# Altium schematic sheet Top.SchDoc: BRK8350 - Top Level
size C; Organization: Opal Kelly; Address1: 13500 SW 72nd Ave STE 100; Address3: Portland, OR  97223; Address4: http://www.opalkelly.com; DocumentNumber: xxx; Revision: 1; SheetNumber: 1; SheetTotal: 7; PageSetup: Record=PageOptions¦CenterHorizontal=True¦CenterVertical=True¦PrintScale=0.52¦XCorrection=1.00¦YCorrection=1.00¦PrintKind=0¦BorderSize=5000000¦LeftOffset=0¦BottomOffset=0¦Orientation=2¦PaperLength=1000¦PaperWidth=1000¦Scale=100¦PaperSource=15¦PrintQuality=600¦MediaType=1¦DitherType=10¦PaperKind=Letter¦PrintScaleMode=1
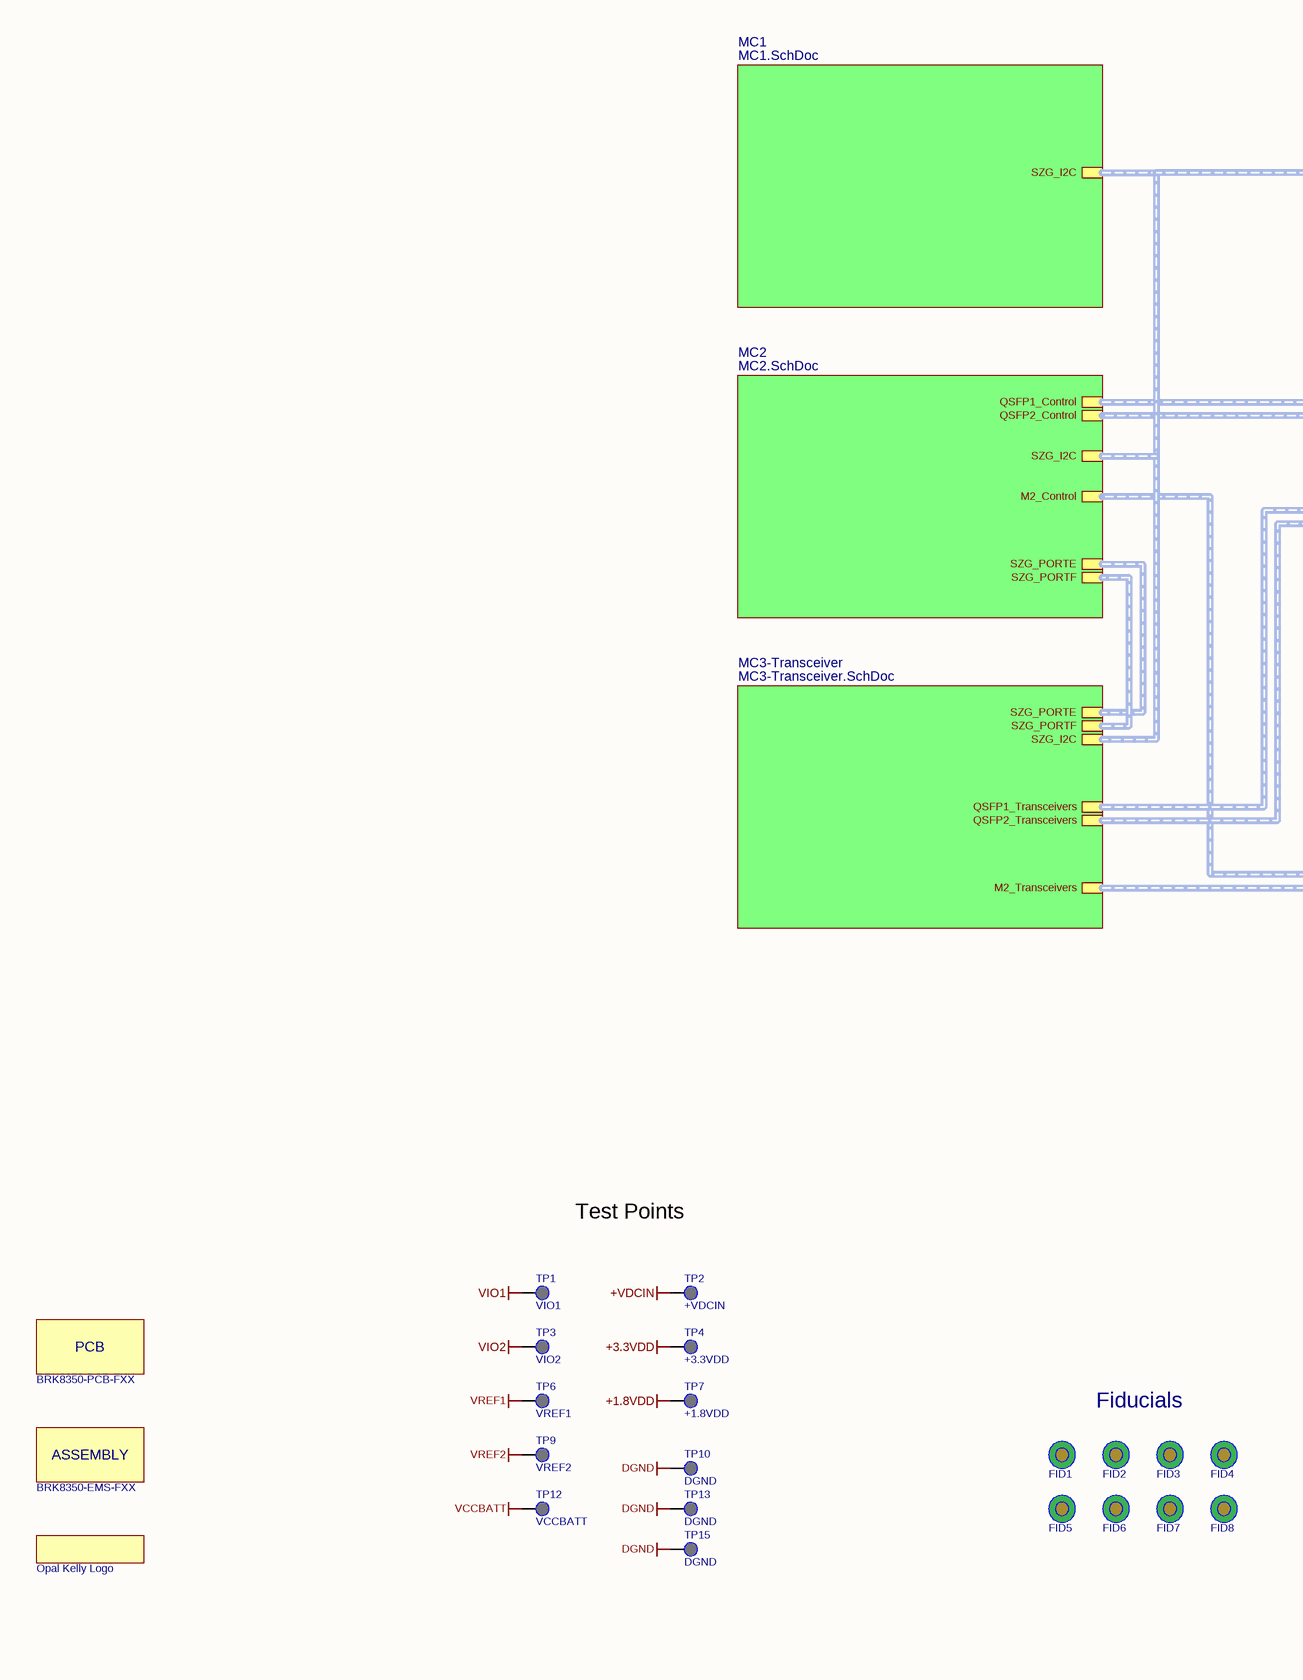
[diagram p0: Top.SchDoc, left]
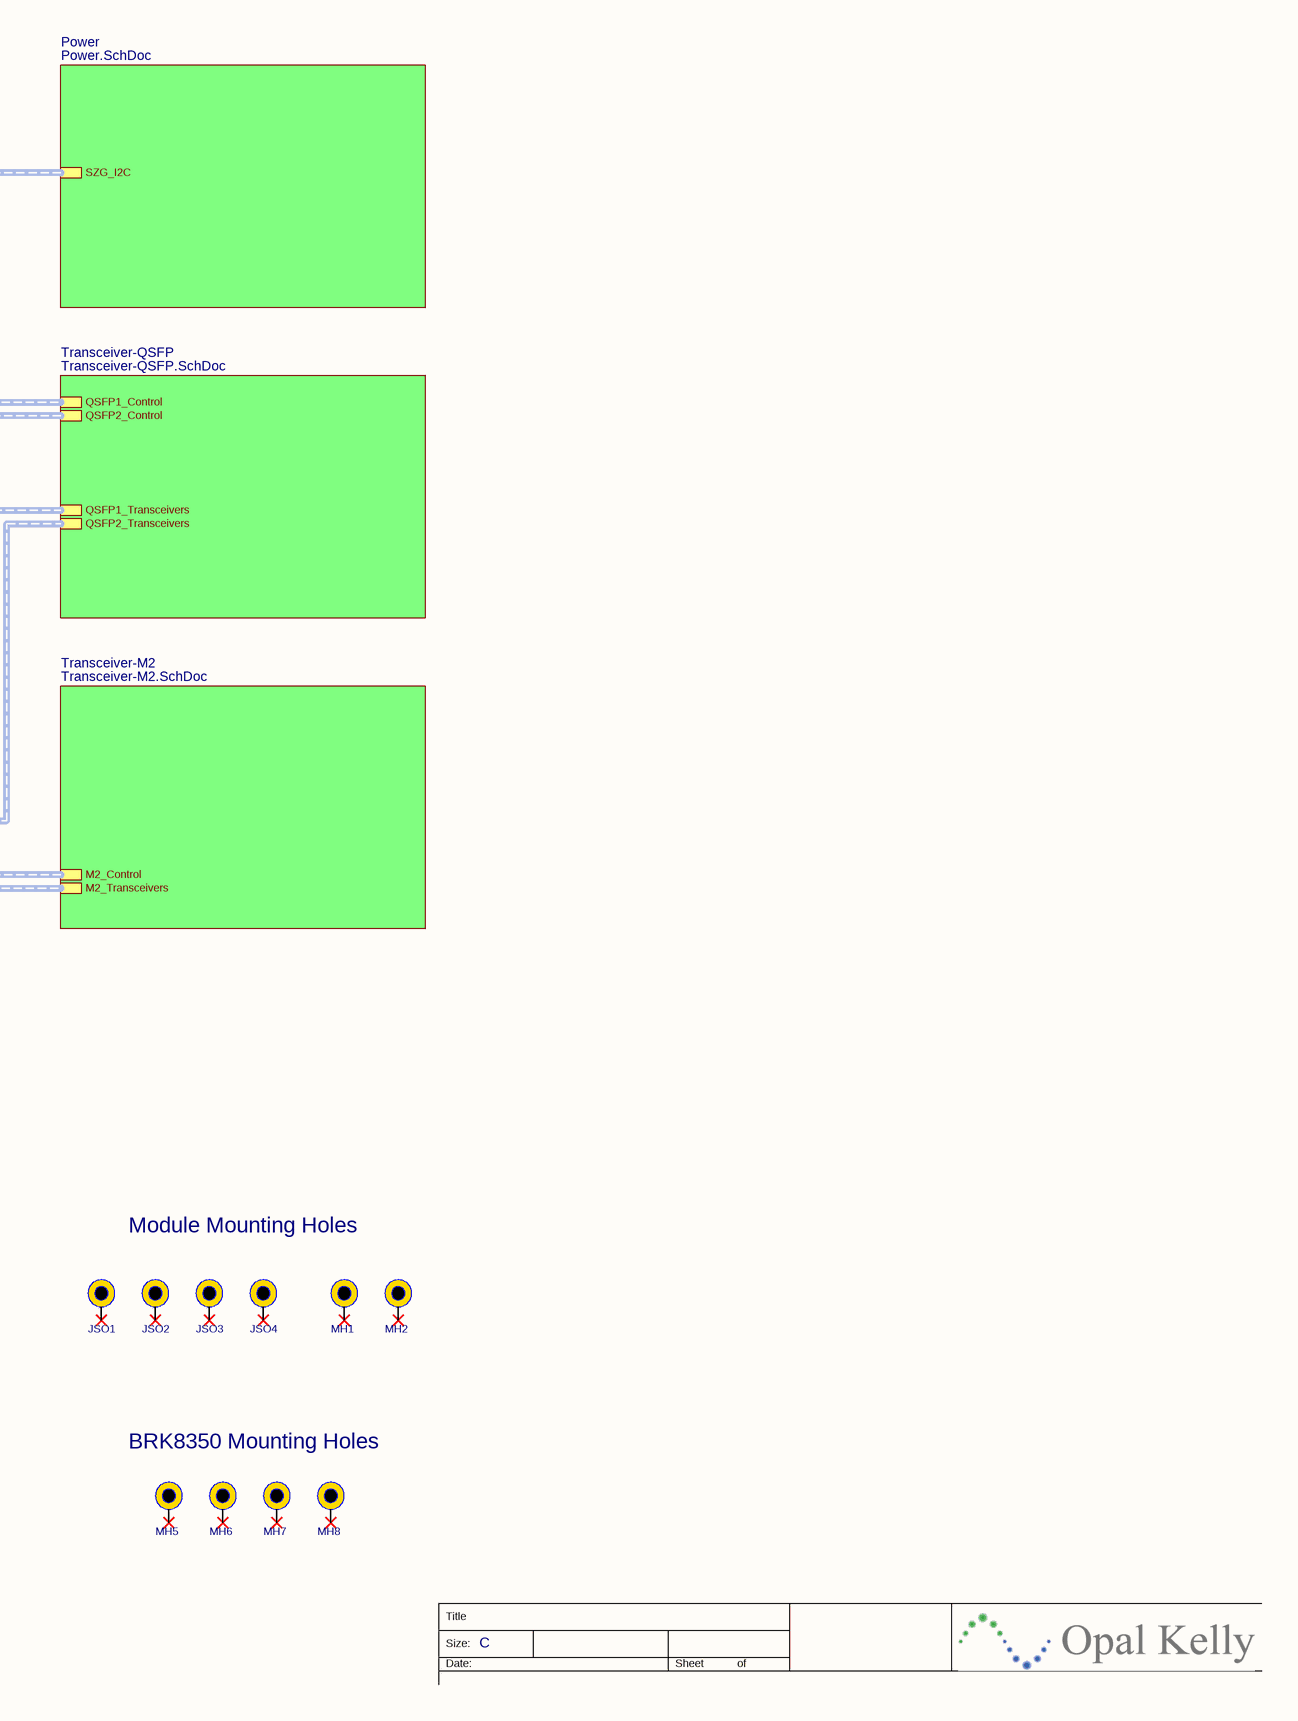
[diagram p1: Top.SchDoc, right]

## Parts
*1  Opal Kelly Logo  [okLogo-23x5]
ASSY1  BRK8350-EMS-FXX  (mechanical)
FID1  FIDUCIAL  [FID1MM/2MM-SS]  (value not drawn)
FID2  FIDUCIAL  [FID1MM/2MM-SS]  (value not drawn)
FID3  FIDUCIAL  [FID1MM/2MM-SS]  (value not drawn)
FID4  FIDUCIAL  [FID1MM/2MM-SS]  (value not drawn)
FID5  FIDUCIAL  [FID1MM/2MM-SS]  (value not drawn)
FID6  FIDUCIAL  [FID1MM/2MM-SS]  (value not drawn)
FID7  FIDUCIAL  [FID1MM/2MM-SS]  (value not drawn)
FID8  FIDUCIAL  [FID1MM/2MM-SS]  (value not drawn)
JSO1  Jack Screw Standoff  [JSO-0515-01]  (value not drawn)
JSO2  Jack Screw Standoff  [JSO-0515-01]  (value not drawn)
JSO3  Jack Screw Standoff  [JSO-0515-01]  (value not drawn)
JSO4  Jack Screw Standoff  [JSO-0515-01]  (value not drawn)
MH1  MTG  [MTG-3.2/6.5-PTH]  (value not drawn)
MH2  MTG  [MTG-3.2/6.5-PTH]  (value not drawn)
MH5  MTG  [MTG-3.2/6.5-PTH]  (value not drawn)
MH6  MTG  [MTG-3.2/6.5-PTH]  (value not drawn)
MH7  MTG  [MTG-3.2/6.5-PTH]  (value not drawn)
MH8  MTG  [MTG-3.2/6.5-PTH]  (value not drawn)
PCB1  BRK8350-PCB-FXX  (mechanical)
TP1  VIO1  [TP-PTH-65/100]
TP2  +VDCIN  [TP-PTH-65/100]
TP3  VIO2  [TP-PTH-65/100]
TP4  +3.3VDD  [TP-PTH-65/100]
TP6  VREF1  [TP-PTH-65/100]
TP7  +1.8VDD  [TP-PTH-65/100]
TP9  VREF2  [TP-PTH-65/100]
TP10  DGND  [TP-PTH-65/100]
TP12  VCCBATT  [TP-PTH-65/100]
TP13  DGND  [TP-PTH-65/100]
TP15  DGND  [TP-PTH-65/100]

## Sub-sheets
MC1 = MC1.SchDoc: SZG_I2C (harness I2C)
MC2 = MC2.SchDoc: SZG_PORTE (harness SYZYGY_TXR4), SZG_PORTF (harness SYZYGY_TXR4), QSFP1_Control (harness QSFP_Control), M2_Control (harness M2_Control), QSFP2_Control (harness QSFP_Control), SZG_I2C (harness I2C)
MC3-Transceiver = MC3-Transceiver.SchDoc: SZG_PORTE (harness SYZYGY_TXR4), SZG_PORTF (harness SYZYGY_TXR4), SZG_I2C (harness I2C), M2_Transceivers (harness M2_Transceivers), QSFP1_Transceivers (harness QSFP_Transceivers), QSFP2_Transceivers (harness QSFP_Transceivers)
Power = Power.SchDoc: SZG_I2C (harness I2C)
Transceiver-M2 = Transceiver-M2.SchDoc: M2_Transceivers (harness M2_Transceivers), M2_Control (harness M2_Control)
Transceiver-QSFP = Transceiver-QSFP.SchDoc: QSFP1_Control (harness QSFP_Control), QSFP2_Control (harness QSFP_Control), QSFP1_Transceivers (harness QSFP_Transceivers), QSFP2_Transceivers (harness QSFP_Transceivers)

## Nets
+1.8VDD: TP7.1(PIN)
+3.3VDD: TP4.1(PIN)
+VDCIN: TP2.1(PIN)
DGND: TP10.1(PIN) TP13.1(PIN) TP15.1(PIN)
VCCBATT: TP12.1(PIN)
VIO1: TP1.1(PIN)
VIO2: TP3.1(PIN)
VREF1: TP6.1(PIN)
VREF2: TP9.1(PIN)

Not connected (* = marked no-connect by the designer): JSO1 1*; JSO2 1*; JSO3 1*; JSO4 1*; MH1 1*; MH2 1*; MH5 1*; MH6 1*; MH7 1*; MH8 1*

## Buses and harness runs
harness sheet MC1/SZG_I2C = sheet MC2/SZG_I2C = sheet MC3-Transceiver/SZG_I2C = sheet Power/SZG_I2C
harness sheet MC2/M2_Control = sheet Transceiver-M2/M2_Control
harness sheet MC2/QSFP1_Control = sheet Transceiver-QSFP/QSFP1_Control
harness sheet MC2/QSFP2_Control = sheet Transceiver-QSFP/QSFP2_Control
harness sheet MC2/SZG_PORTE = sheet MC3-Transceiver/SZG_PORTE
harness sheet MC2/SZG_PORTF = sheet MC3-Transceiver/SZG_PORTF
harness sheet MC3-Transceiver/M2_Transceivers = sheet Transceiver-M2/M2_Transceivers
harness sheet MC3-Transceiver/QSFP1_Transceivers = sheet Transceiver-QSFP/QSFP1_Transceivers
harness sheet MC3-Transceiver/QSFP2_Transceivers = sheet Transceiver-QSFP/QSFP2_Transceivers

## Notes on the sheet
- Test Points
- Module Mounting Holes
- Fiducials
- BRK8350 Mounting Holes
- Title
- Size:
- Date:
- C
- Sheet
- of

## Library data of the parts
*1 = OKLOGO: partnumber: ALIGNI_IGNORE
ASSY1 = 001974: Assembly Service; Partnumber: 001974; manufacturer: PCB Assembly Cost; description: BRK8350 PCB assembly
FID1-FID8 = FIDUCIAL: PCB fiducial; partnumber: ALIGNI_IGNORE
JSO1-JSO4 = 001879: Mounting hole; Partnumber: 001879; manufacturer: Samtec
MH1 MH2 MH5-MH8 = MTG: Mounting hole; partnumber: ALIGNI_IGNORE
PCB1 = 001975: PCB; Partnumber: 001975; manufacturer: Generic PCB Manufacturer; description: PCB for BRK8350
TP1-TP4 TP6 TP7 TP9 TP10 TP12 TP13 TP15 = TP-PTH-65/100: Test point, plated through-hole, 65/100mil; partnumber: ALIGNI_IGNORE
